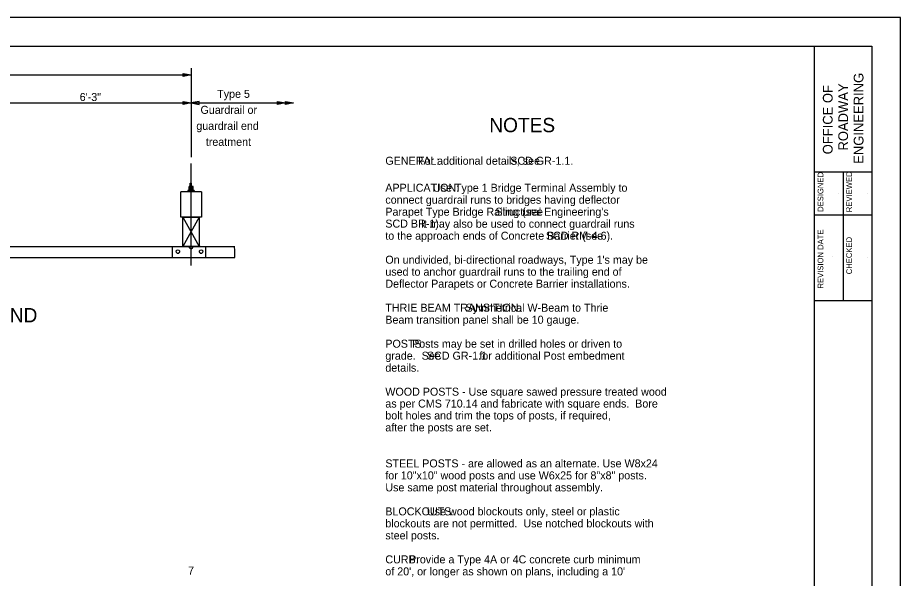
# Model space of a CAD drawing. Extents: x 0 to 34, y 0 to 22.
# Drawn here: x 18.56 to 34, y 12.19 to 22 of the extents above; entities that cross this region are included whole.
import ezdxf

# ---------------------------------------------------------------- set-up
doc = ezdxf.new("R2010")
doc.units = 0
for name, color, linetype in [('SH_Border', 7, 'Continuous'), ('SH_Cut_Line', 7, 'Continuous'), ('SH_Data', 7, 'Continuous'), ('ST_Details', 7, 'Continuous'), ('ST_Text', 7, 'Continuous')]:
    doc.layers.add(name, color=color, linetype=linetype)

msp = doc.modelspace()

# ---------------------------------------------------------------- linework, layer by layer
at = {"layer": 'SH_Border'}
for p, q in [((32.5, 0.5), (32.5, 21.5)), ((32.5, 19.3), (33.5, 19.3)), ((33, 19.3), (33, 17.05)), ((32.5, 18.55), (33.5, 18.55)), ((32.5, 17.05), (33.5, 17.05))]:
    msp.add_line(p, q, dxfattribs=at)
msp.add_lwpolyline([(2, 21.5), (33.5, 21.5), (33.5, 0.5), (2, 0.5)], close=True, dxfattribs=at)
at = {"layer": 'SH_Cut_Line'}
msp.add_lwpolyline([(0, 0), (34, 0), (34, 22), (0, 22)], close=True, dxfattribs=at)
at = {"layer": 'SH_Data'}
for p, q in [((32.92, 18.929), (32.92, 18.929)), ((33.42, 18.929), (33.42, 18.929)), ((32.807, 17.828), (32.807, 17.828)), ((33.42, 17.804), (33.42, 17.804))]:
    msp.add_line(p, q, dxfattribs=at)
at = {"layer": 'ST_Details'}
for p, q in [((21.591, 19.445), (21.591, 17.66)), ((21.629, 19.043), (21.558, 19.043)), ((21.558, 18.978), (21.558, 19.043)), ((21.579, 19.101), (21.586, 19.102)), ((21.579, 19.05), (21.579, 19.101)), ((21.604, 19.096), (21.579, 19.096)), ((21.604, 19.09), (21.579, 19.09)), ((21.604, 19.082), (21.579, 19.082)), ((21.579, 18.977), (21.579, 19.022)), ((21.597, 19.102), (21.589, 19.102)), ((21.604, 19.099), (21.597, 19.102)), ((21.604, 19.048), (21.604, 19.099)), ((21.605, 18.977), (21.605, 19.022)), ((21.629, 18.976), (21.629, 19.043)), ((21.413, 18.509), (21.413, 18.953)), ((21.775, 18.953), (21.413, 18.953)), ((21.647, 18.96), (21.536, 18.96)), ((21.647, 18.977), (21.539, 18.977)), ((21.539, 18.977), (21.539, 18.96)), ((21.647, 18.977), (21.647, 18.96)), ((21.775, 18.953), (21.775, 18.509)), ((21.775, 18.509), (21.413, 18.509)), ((21.451, 17.993), (21.451, 18.509)), ((21.451, 18.509), (21.737, 18.509)), ((21.451, 18.509), (21.737, 17.993)), ((21.737, 18.509), (21.451, 17.993)), ((21.737, 18.509), (21.737, 17.993)), ((4.502, 17.993), (21.269, 17.993)), ((21.269, 17.993), (22.358, 17.993)), ((21.269, 17.8), (21.269, 17.993)), ((21.736, 17.993), (21.45, 17.993)), ((21.737, 17.993), (21.451, 17.993)), ((21.751, 17.993), (21.465, 17.993)), ((21.854, 17.8), (21.854, 17.993)), ((5.407, 17.8), (21.269, 17.8)), ((21.269, 17.8), (22.358, 17.8))]:
    msp.add_line(p, q, dxfattribs=at)
for centre, major_axis, ratio, start_param, end_param in [((21.568, 19.026), (0, -0.0142), 0.738563, 1.441228, 4.934001), ((21.593, 19.025), (0, -0.0169), 0.738563, 1.385306, 4.820506), ((21.617, 19.023), (0, -0.0162), 0.738563, 1.407193, 4.875853), ((21.364, 17.91), (-0.0342, 0), 0.599655, 3.141593, 6.283185), ((21.364, 17.91), (0.0342, 0), 0.943283, 3.141593, 6.283185), ((21.595, 17.989), (0.0342, 0), 0.943283, 3.141593, 6.283185), ((21.769, 17.91), (-0.0342, 0), 0.599655, 3.141593, 6.283185), ((21.769, 17.91), (0.0342, 0), 0.943283, 3.141593, 6.283185)]:
    msp.add_ellipse(centre, major_axis=major_axis, ratio=ratio, start_param=start_param, end_param=end_param, dxfattribs=at)
msp.add_spline([(22.357, 17.8), (22.362, 17.9), (22.351, 17.997)], degree=3, dxfattribs=at)
at = {"layer": 'ST_Text'}
for p, q in [((21.594, 21.115), (21.594, 19.559)), ((4.161, 20.997), (21.594, 20.997)), ((18.232, 20.506), (23.387, 20.506)), ((23.29, 20.506), (23.387, 20.506))]:
    msp.add_line(p, q, dxfattribs=at)
for points in [[(21.454, 20.969), (21.454, 21.025), (21.594, 20.997)], [(21.454, 20.478), (21.454, 20.534), (21.594, 20.506)], [(21.734, 20.478), (21.734, 20.534), (21.594, 20.506)], [(23.107, 20.478), (23.107, 20.534), (23.247, 20.506)], [(23.247, 20.478), (23.247, 20.534), (23.387, 20.506)]]:
    msp.add_lwpolyline(points, close=True, dxfattribs=at)

# ---------------------------------------------------------------- texts
at = {"layer": 'SH_Data'}
for s, height, p in [('ENGINEERING', 0.17, (33.355, 19.442)), ('ROADWAY', 0.17, (33.085, 19.674)), ('OFFICE OF', 0.17, (32.815, 19.608)), ('REVIEWED', 0.1, (33.153, 18.595)), ('DESIGNED', 0.1, (32.653, 18.6)), ('REVISION DATE', 0.1, (32.653, 17.259)), ('CHECKED', 0.1, (33.153, 17.508))]:
    msp.add_text(s, height=height, rotation=90, dxfattribs=at).set_placement(p)
at = {"layer": 'ST_Text'}
for s, height, p in [('Type 5', 0.14, (22.051, 20.596)), ('6\'-3"', 0.14, (19.646, 20.541)), ('Guardrail or', 0.14, (21.759, 20.316)), (' NOTES', 0.25, (26.717, 19.995)), ('guardrail end', 0.14, (21.686, 20.036)), ('treatment', 0.14, (21.852, 19.756)), ('GENERAL:', 0.14, (24.992, 19.425)), ('           For additional details, see', 0.14, (24.992, 19.425)), ('                                          SCD GR-1.1.', 0.14, (24.992, 19.425)), ('APPLICATION:', 0.14, (24.992, 18.953)), ('                Use Type 1 Bridge Terminal Assembly to', 0.14, (24.992, 18.953)), ('connect guardrail runs to bridges having deflector', 0.14, (24.992, 18.743)), ('Parapet Type Bridge Railing (see', 0.14, (24.992, 18.533)), ("                                     Structural Engineering's ", 0.14, (24.992, 18.533)), ('SCD BR-1).', 0.14, (24.992, 18.325)), ('            It may also be used to connect guardrail runs', 0.14, (24.992, 18.323)), ('to the approach ends of Concrete Barrier (see', 0.14, (24.992, 18.113)), ('                                                      SCD RM-4.6).', 0.14, (24.992, 18.113)), ("On undivided, bi-directional roadways, Type 1's may be", 0.14, (24.992, 17.693)), ('used to anchor guardrail runs to the trailing end of', 0.14, (24.992, 17.483)), ('Deflector Parapets or Concrete Barrier installations.', 0.14, (24.992, 17.273)), ('THRIE BEAM TRANSITION:', 0.14, (24.992, 16.853)), ('                           Symmetrical W-Beam to Thrie', 0.14, (24.992, 16.853)), ('LEGEND', 0.25, (17.531, 16.667)), ('Beam transition panel shall be 10 gauge.', 0.14, (24.992, 16.643)), ('         Posts may be set in drilled holes or driven to', 0.14, (24.992, 16.223)), ('POSTS:', 0.14, (24.992, 16.223)), ('grade.  See             for additional Post embedment', 0.14, (24.992, 16.013)), ('              SCD GR-1.1', 0.14, (24.992, 16.013)), ('details.', 0.14, (24.992, 15.803)), ('WOOD POSTS - Use square sawed pressure treated wood', 0.14, (24.992, 15.383)), ('as per CMS 710.14 and fabricate with square ends.  Bore', 0.14, (24.992, 15.175)), ('bolt holes and trim the tops of posts, if required,', 0.14, (24.992, 14.967)), ('after the posts are set.', 0.14, (24.992, 14.758)), ('STEEL POSTS - are allowed as an alternate. Use W8x24', 0.14, (24.992, 14.128)), ('for 10"x10" wood posts and use W6x25 for 8"x8" posts.  ', 0.14, (24.992, 13.918)), ('Use same post material throughout assembly.', 0.14, (24.992, 13.708)), ('              Use wood blockouts only, steel or plastic', 0.14, (24.992, 13.288)), ('BLOCKOUTS:', 0.14, (24.992, 13.288)), ('blockouts are not permitted.  Use notched blockouts with', 0.14, (24.992, 13.078)), ('steel posts.', 0.14, (24.992, 12.868)), ('CURB:', 0.14, (24.992, 12.448)), ('        Provide a Type 4A or 4C concrete curb minimum', 0.14, (24.992, 12.448)), ('7', 0.14, (21.542, 12.253)), ("of 20', or longer as shown on plans, including a 10' ", 0.14, (24.992, 12.238))]:
    msp.add_text(s, height=height, dxfattribs=at).set_placement(p)

doc.saveas('drawing.dxf')
